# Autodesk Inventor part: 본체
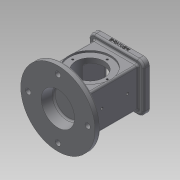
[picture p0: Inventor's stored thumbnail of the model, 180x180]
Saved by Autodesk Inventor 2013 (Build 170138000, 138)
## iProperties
Created: 2018-10
Part Number: 본체
Material: 일반
Document SubType Name: Modeling
Designer: Administrator
Density: 1 g/cm^3
Mass: 364.657 g
Surface Area: 743.905 cm^2
Volume: 364.657 cm^3
Author: Administrator
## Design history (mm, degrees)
sketch "스케치1"
  geometry: C1 r 62.5 at (0, 0); 1 further point
  constraints: 1 centre point, 1 coincident
  dimensions: "d0" = 125 diameter of C1
extrude "돌출1" new body sketch "스케치1" distance "d1" = 10; taper "d2" = 0 deg
sketch "스케치2"
  geometry: L1 (-37, -33)-(37, -33); L2 (37, -33)-(37, 33); L3 (37, 33)-(-37, 33); L4 (-37, 33)-(-37, -33); L5 (-37, -33)-(37, 33); L6 (37, -33)-(-37, 33); C1 r 62.5 at (0, 0) reference
  constraints: 12 end point, 2 midpoint, 2 parallel, 1 horizontal, 1 perpendicular
  dimensions: "d3" = 74 distance of L3.end L2.end; "d4" = 66 distance of L2.end L1.end
extrude "돌출2" join sketch "스케치2" distance "d5" = 88; taper "d6" = 0 deg
sketch "스케치3"
  geometry: L1 (-46, -41)-(46, -41); L2 (46, -41)-(46, 41); L3 (46, 41)-(-46, 41); L4 (-46, 41)-(-46, -41); L5 (-46, -41)-(46, 41); L6 (46, -41)-(-46, 41); 1 further point
  constraints: 12 end point, 2 midpoint, 2 parallel, 1 horizontal, 1 perpendicular
  dimensions: "d7" = 92 distance of L3.end L2.end; "d8" = 82 distance of L2.end L1.end
extrude "돌출3" join sketch "스케치3" distance "d9" = 10; taper "d10" = 0 deg
sketch "스케치4"
  geometry: L1 (26, -26)-(-26, -26); L2 (-26, -26)-(-26, 26); L3 (-26, 26)-(26, 26); L4 (26, 26)-(26, -26); L5 (26, -26)-(-26, 26); L6 (-26, -26)-(26, 26); 1 further point
  constraints: 12 end point, 2 midpoint, 2 parallel, 1 horizontal, 1 perpendicular
  dimensions: "d11" = 52 distance of L2.end L3.end; "d12" = 52 distance of L1.end L2.end
extrude "돌출4" cut sketch "스케치4" distance "d13" = 8; taper "d14" = 0 deg
sketch "스케치5"
  geometry: L1 (22, -22)-(-22, -22); L2 (-22, -22)-(-22, 22); L3 (-22, 22)-(22, 22); L4 (22, 22)-(22, -22); L5 (22, -22)-(-22, 22); L6 (-22, -22)-(22, 22); 1 further point
  constraints: 12 end point, 2 midpoint, 2 parallel, 1 horizontal, 1 perpendicular
  dimensions: "d15" = 44 distance of L2.end L3.end; "d16" = 44 distance of L1.end L2.end
extrude "돌출5" cut sketch "스케치5" distance "d17" = 74; taper "d18" = 0 deg
sketch "스케치6"
  geometry: C1 r 62.5 at (0, 0) reference; C2 r 28 at (0, 0)
  constraints: 1 centre point, 1 coincident
  dimensions: "d19" = 56 diameter of C2
extrude "돌출6" cut sketch "스케치6" distance "d20" = 18; taper "d21" = -10 deg
sketch "스케치7"
  geometry: C1 r 62.5 at (0, 0) reference; C2 r 4.5 at (-50, 0)
  constraints: 1 centre point, 1 horizontal alignment
  dimensions: "d22" = 9 diameter of C2; "d23" = 50 distance of C2.centre C1.centre
extrude "돌출7" cut sketch "스케치7" distance "d24" = 18; taper "d25" = 0 deg
fillet "모깎기1" dims "d29" = 3, "d30" = 10
fillet "모깎기2" dims "d31" = 3
sketch "스케치8"
  geometry: L1 (-28.5, -13)-(96.5, -13) reference; C1 r 35 at (34, 41); 1 further point
  constraints: 1 centre point, 1 vertical alignment
  dimensions: "d32" = 70 diameter of C1; "d33" = 54 distance from line of L1 C1.centre
extrude "돌출8" cut sketch "스케치8" distance "d34" = 3; taper "d35" = 0 deg
sketch "스케치9"
  geometry: C1 r 35 at (0, 0) reference; C2 r 24 at (0, 0); 1 further point
  constraints: 1 centre point, 1 coincident
  dimensions: "d36" = 48 diameter of C2
fillet "모깎기3" dims "d37" = 3
fillet "모깎기4" dims "d38" = 3
extrude "돌출9" cut sketch "스케치9" stored distance "d39" = 3; taper "d40" = 0 deg
sketch "스케치10"
  geometry: A1 r 10 centre (-36, -31) between (-46, -31) and (-36, -41) reference; A2 r 10 centre (36, -31) between (36, -41) and (46, -31) reference; A3 r 10 centre (36, 31) between (46, 31) and (36, 41) reference; A4 r 10 centre (-36, 31) between (-36, 41) and (-46, 31) reference; 1 further point
hole "구멍1" sketch "스케치10" at (-36, 31), (36, 31), (36, -31), (-36, -31) diameter "d41" = 3.242; stored, may be unused: countersink angle "d45" = 90 deg, drill point angle "d47" = 118 deg; dims "d42" = 4, "d43" = 4, "d44" = 2, "d46" = 6
sketch "스케치11"
  geometry: C1 r 24 at (0, 0) reference; 2 further points
  constraints: 1 vertical alignment
  dimensions: "d48" = 29 distance of point (0, 29) C1.centre
hole "구멍2" sketch "스케치11" at (0, 29) diameter "d49" = 3.242; stored, may be unused: countersink angle "d53" = 90 deg, drill point angle "d55" = 118 deg; dims "d50" = 4, "d51" = 4, "d52" = 2, "d54" = 6
sketch "스케치12"
  geometry: L1 (0, 0)-(72, 0) reference; L2 (17, -8)-(17, -39.337) reference; 3 further points
  constraints: 1 vertical alignment, 2 other
  dimensions: "d59" = 4 distance from line of L1 point (36, -4)
feature "엠보싱1" sketch "스케치12" dims "d60" = 0.5, "d61" = 0
sketch "스케치13"
  geometry: L1 (-92.5, -13)-(32.5, -13) reference; 3 further points
  constraints: 2 vertical alignment
  dimensions: "d62" = 37 distance from line of L1 point (-30, 24); "d63" = 43 distance of point (-30, 24) point (-30, 67)
hole "구멍3" sketch "스케치13" at (-30, 67), (-30, 24) diameter "d64" = 4.134; stored, may be unused: countersink angle "d68" = 90 deg, drill point angle "d70" = 118 deg; dims "d65" = 30, "d66" = 4, "d67" = 2, "d69" = 30
chamfer "모따기1" distance "d71" = 1; stored, may be unused: second distance "d72" = 2, angle "d73" = 45 deg
node "솔리드1"
pattern_circular "원형 패턴1" dims angle "d27" = 360 deg
mirror "대칭1"
pattern_circular "원형 패턴2" dims angle "d57" = 360 deg
mirror "대칭2"
